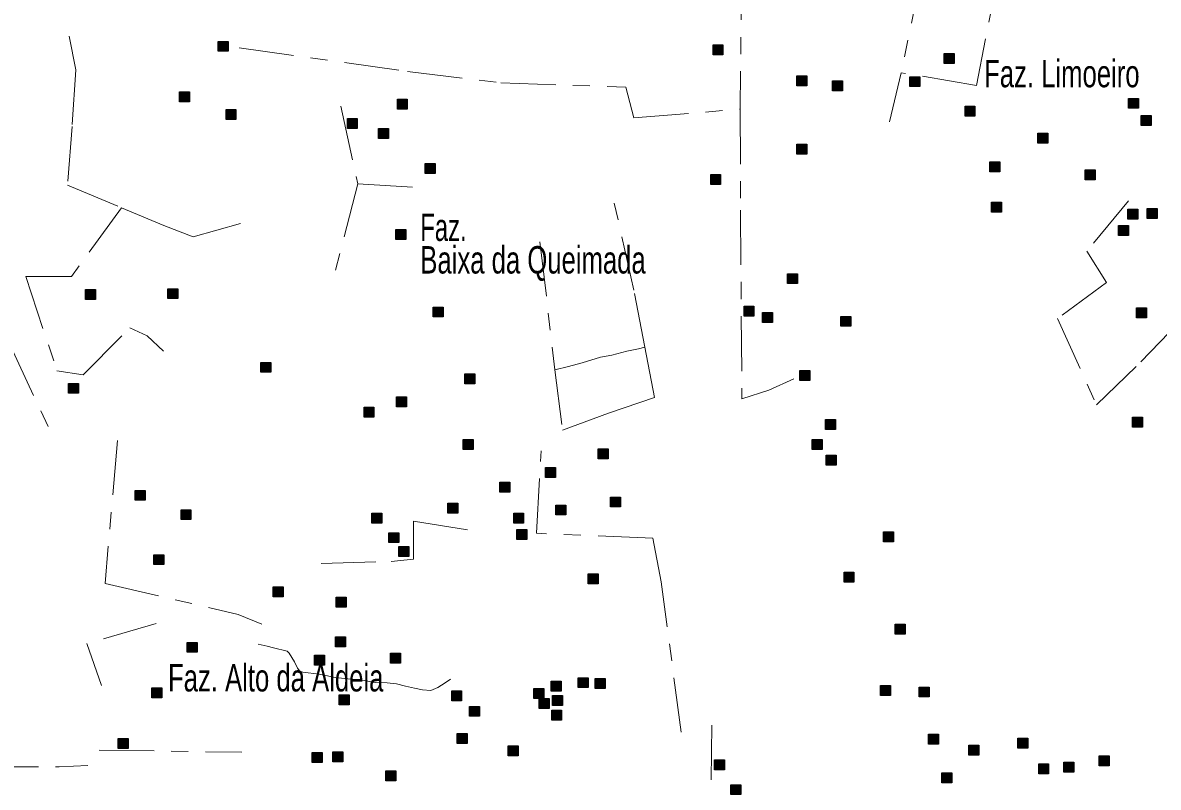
# Model space of a CAD drawing. Extents: x 445.4 to 500, y 8728.7 to 8784.
# Drawn here: x 475.26 to 481.88, y 8770.25 to 8774.71 of the extents above; entities that cross this region are included whole.
import ezdxf

# ---------------------------------------------------------------- set-up
doc = ezdxf.new("R2010")
doc.units = 0
doc.header["$LTSCALE"] = 0.064
doc.linetypes.add('DOT_DASHED', pattern=[7.7, 5, -1.2, 0.3, -1.2])
doc.layers.add('2', color=7, linetype='Continuous', lineweight=25)
doc.layers.add('22', color=7, linetype='DOT_DASHED', lineweight=13)
doc.layers.add('61', color=7, linetype='Continuous')

msp = doc.modelspace()

# ---------------------------------------------------------------- hatches: boundary and pattern name
at = {"layer": '2'}
for points in [[(476.3995, 8774.601), (476.4575, 8774.601), (476.4575, 8774.543), (476.3995, 8774.543)], [(479.2865, 8774.5802), (479.3445, 8774.5802), (479.3445, 8774.5222), (479.2865, 8774.5222)], [(480.635, 8774.5304), (480.693, 8774.5304), (480.693, 8774.4724), (480.635, 8774.4724)], [(479.7752, 8774.3991), (479.8332, 8774.3991), (479.8332, 8774.3411), (479.7752, 8774.3411)], [(479.9838, 8774.3707), (480.0418, 8774.3707), (480.0418, 8774.3127), (479.9838, 8774.3127)], [(480.4359, 8774.3945), (480.4939, 8774.3945), (480.4939, 8774.3365), (480.4359, 8774.3365)], [(476.1733, 8774.3067), (476.2313, 8774.3067), (476.2313, 8774.2487), (476.1733, 8774.2487)], [(477.4448, 8774.2632), (477.5028, 8774.2632), (477.5028, 8774.2052), (477.4448, 8774.2052)], [(481.7119, 8774.2681), (481.7699, 8774.2681), (481.7699, 8774.2101), (481.7119, 8774.2101)], [(476.4448, 8774.2026), (476.5028, 8774.2026), (476.5028, 8774.1446), (476.4448, 8774.1446)], [(480.7571, 8774.2225), (480.8151, 8774.2225), (480.8151, 8774.1645), (480.7571, 8774.1645)], [(477.1529, 8774.1498), (477.2109, 8774.1498), (477.2109, 8774.0918), (477.1529, 8774.0918)], [(481.7843, 8774.1685), (481.8423, 8774.1685), (481.8423, 8774.1105), (481.7843, 8774.1105)], [(477.3353, 8774.0926), (477.3933, 8774.0926), (477.3933, 8774.0346), (477.3353, 8774.0346)], [(481.1825, 8774.0643), (481.2405, 8774.0643), (481.2405, 8774.0063), (481.1825, 8774.0063)], [(479.7752, 8774.0007), (479.8332, 8774.0007), (479.8332, 8773.9427), (479.7752, 8773.9427)], [(477.6077, 8773.8875), (477.6657, 8773.8875), (477.6657, 8773.8295), (477.6077, 8773.8295)], [(480.9019, 8773.8968), (480.9599, 8773.8968), (480.9599, 8773.8388), (480.9019, 8773.8388)], [(481.4585, 8773.8515), (481.5165, 8773.8515), (481.5165, 8773.7935), (481.4585, 8773.7935)], [(479.2729, 8773.8241), (479.3309, 8773.8241), (479.3309, 8773.7661), (479.2729, 8773.7661)], [(480.911, 8773.6614), (480.969, 8773.6614), (480.969, 8773.6034), (480.911, 8773.6034)], [(481.7074, 8773.6206), (481.7654, 8773.6206), (481.7654, 8773.5626), (481.7074, 8773.5626)], [(481.8205, 8773.6252), (481.8785, 8773.6252), (481.8785, 8773.5672), (481.8205, 8773.5672)], [(481.6531, 8773.5256), (481.7111, 8773.5256), (481.7111, 8773.4676), (481.6531, 8773.4676)], [(477.4358, 8773.5026), (477.4938, 8773.5026), (477.4938, 8773.4446), (477.4358, 8773.4446)], [(479.7209, 8773.2446), (479.7789, 8773.2446), (479.7789, 8773.1866), (479.7209, 8773.1866)], [(475.6257, 8773.1523), (475.6837, 8773.1523), (475.6837, 8773.0943), (475.6257, 8773.0943)], [(476.1054, 8773.1568), (476.1634, 8773.1568), (476.1634, 8773.0988), (476.1054, 8773.0988)], [(477.653, 8773.0499), (477.711, 8773.0499), (477.711, 8772.9919), (477.653, 8772.9919)], [(479.4675, 8773.0544), (479.5255, 8773.0544), (479.5255, 8772.9964), (479.4675, 8772.9964)], [(481.7572, 8773.0457), (481.8152, 8773.0457), (481.8152, 8772.9877), (481.7572, 8772.9877)], [(479.5761, 8773.0182), (479.6341, 8773.0182), (479.6341, 8772.9602), (479.5761, 8772.9602)], [(480.0331, 8772.9956), (480.0911, 8772.9956), (480.0911, 8772.9376), (480.0331, 8772.9376)], [(476.6484, 8772.7267), (476.7064, 8772.7267), (476.7064, 8772.6687), (476.6484, 8772.6687)], [(477.8385, 8772.6605), (477.8965, 8772.6605), (477.8965, 8772.6025), (477.8385, 8772.6025)], [(479.7933, 8772.6786), (479.8513, 8772.6786), (479.8513, 8772.6206), (479.7933, 8772.6206)], [(475.5262, 8772.6044), (475.5842, 8772.6044), (475.5842, 8772.5464), (475.5262, 8772.5464)], [(477.4403, 8772.5247), (477.4983, 8772.5247), (477.4983, 8772.4667), (477.4403, 8772.4667)], [(477.2503, 8772.4658), (477.3083, 8772.4658), (477.3083, 8772.4078), (477.2503, 8772.4078)], [(479.9426, 8772.3934), (480.0006, 8772.3934), (480.0006, 8772.3354), (479.9426, 8772.3354)], [(481.7345, 8772.4073), (481.7925, 8772.4073), (481.7925, 8772.3493), (481.7345, 8772.3493)], [(477.8295, 8772.2757), (477.8875, 8772.2757), (477.8875, 8772.2177), (477.8295, 8772.2177)], [(479.8657, 8772.2757), (479.9237, 8772.2757), (479.9237, 8772.2177), (479.8657, 8772.2177)], [(478.6168, 8772.2214), (478.6748, 8772.2214), (478.6748, 8772.1634), (478.6168, 8772.1634)], [(479.9472, 8772.1851), (480.0052, 8772.1851), (480.0052, 8772.1271), (479.9472, 8772.1271)], [(478.3091, 8772.1127), (478.3671, 8772.1127), (478.3671, 8772.0547), (478.3091, 8772.0547)], [(478.0421, 8772.0267), (478.1001, 8772.0267), (478.1001, 8771.9687), (478.0421, 8771.9687)], [(475.9153, 8771.9796), (475.9733, 8771.9796), (475.9733, 8771.9216), (475.9153, 8771.9216)], [(478.6892, 8771.9407), (478.7472, 8771.9407), (478.7472, 8771.8827), (478.6892, 8771.8827)], [(476.1823, 8771.8665), (476.2403, 8771.8665), (476.2403, 8771.8085), (476.1823, 8771.8085)], [(477.739, 8771.9044), (477.797, 8771.9044), (477.797, 8771.8464), (477.739, 8771.8464)], [(478.3692, 8771.8938), (478.4272, 8771.8938), (478.4272, 8771.8358), (478.3692, 8771.8358)], [(477.2955, 8771.8456), (477.3535, 8771.8456), (477.3535, 8771.7876), (477.2955, 8771.7876)], [(478.1236, 8771.8456), (478.1816, 8771.8456), (478.1816, 8771.7876), (478.1236, 8771.7876)], [(477.3951, 8771.7324), (477.4531, 8771.7324), (477.4531, 8771.6744), (477.3951, 8771.6744)], [(478.1417, 8771.7505), (478.1997, 8771.7505), (478.1997, 8771.6925), (478.1417, 8771.6925)], [(480.282, 8771.7369), (480.34, 8771.7369), (480.34, 8771.6789), (480.282, 8771.6789)], [(476.0239, 8771.6039), (476.0819, 8771.6039), (476.0819, 8771.5459), (476.0239, 8771.5459)], [(477.4539, 8771.6509), (477.5119, 8771.6509), (477.5119, 8771.5929), (477.4539, 8771.5929)], [(478.558, 8771.4924), (478.616, 8771.4924), (478.616, 8771.4344), (478.558, 8771.4344)], [(480.0512, 8771.5015), (480.1092, 8771.5015), (480.1092, 8771.4435), (480.0512, 8771.4435)], [(476.7208, 8771.4155), (476.7788, 8771.4155), (476.7788, 8771.3575), (476.7208, 8771.3575)], [(477.0874, 8771.3566), (477.1454, 8771.3566), (477.1454, 8771.2986), (477.0874, 8771.2986)], [(480.3499, 8771.1982), (480.4079, 8771.1982), (480.4079, 8771.1402), (480.3499, 8771.1402)], [(477.0836, 8771.1247), (477.1416, 8771.1247), (477.1416, 8771.0667), (477.0836, 8771.0667)], [(476.2185, 8771.0923), (476.2765, 8771.0923), (476.2765, 8771.0343), (476.2185, 8771.0343)], [(476.9607, 8771.0171), (477.0187, 8771.0171), (477.0187, 8770.9591), (476.9607, 8770.9591)], [(477.4043, 8771.0284), (477.4623, 8771.0284), (477.4623, 8770.9704), (477.4043, 8770.9704)], [(478.3417, 8770.866), (478.3997, 8770.866), (478.3997, 8770.808), (478.3417, 8770.808)], [(478.4992, 8770.8858), (478.5572, 8770.8858), (478.5572, 8770.8278), (478.4992, 8770.8278)], [(478.5987, 8770.8812), (478.6567, 8770.8812), (478.6567, 8770.8232), (478.5987, 8770.8232)], [(476.0123, 8770.8271), (476.0703, 8770.8271), (476.0703, 8770.7691), (476.0123, 8770.7691)], [(477.7616, 8770.8088), (477.8196, 8770.8088), (477.8196, 8770.7508), (477.7616, 8770.7508)], [(478.2412, 8770.8224), (478.2992, 8770.8224), (478.2992, 8770.7644), (478.2412, 8770.7644)], [(480.2639, 8770.8405), (480.3219, 8770.8405), (480.3219, 8770.7825), (480.2639, 8770.7825)], [(480.4902, 8770.8314), (480.5482, 8770.8314), (480.5482, 8770.7734), (480.4902, 8770.7734)], [(477.1055, 8770.7862), (477.1635, 8770.7862), (477.1635, 8770.7282), (477.1055, 8770.7282)], [(478.2729, 8770.7635), (478.3309, 8770.7635), (478.3309, 8770.7055), (478.2729, 8770.7055)], [(478.3498, 8770.7816), (478.4078, 8770.7816), (478.4078, 8770.7236), (478.3498, 8770.7236)], [(477.8657, 8770.7183), (477.9237, 8770.7183), (477.9237, 8770.6603), (477.8657, 8770.6603)], [(478.3453, 8770.6956), (478.4033, 8770.6956), (478.4033, 8770.6376), (478.3453, 8770.6376)], [(475.8158, 8770.5309), (475.8738, 8770.5309), (475.8738, 8770.4729), (475.8158, 8770.4729)], [(477.7933, 8770.5598), (477.8513, 8770.5598), (477.8513, 8770.5018), (477.7933, 8770.5018)], [(480.5445, 8770.5553), (480.6025, 8770.5553), (480.6025, 8770.4973), (480.5445, 8770.4973)], [(481.0648, 8770.5329), (481.1228, 8770.5329), (481.1228, 8770.4749), (481.0648, 8770.4749)], [(478.0919, 8770.4874), (478.1499, 8770.4874), (478.1499, 8770.4294), (478.0919, 8770.4294)], [(480.7798, 8770.4919), (480.8378, 8770.4919), (480.8378, 8770.4339), (480.7798, 8770.4339)], [(476.9483, 8770.449), (477.0063, 8770.449), (477.0063, 8770.391), (476.9483, 8770.391)], [(477.0684, 8770.4521), (477.1264, 8770.4521), (477.1264, 8770.3941), (477.0684, 8770.3941)], [(479.2956, 8770.4059), (479.3536, 8770.4059), (479.3536, 8770.3479), (479.2956, 8770.3479)], [(481.54, 8770.4288), (481.598, 8770.4288), (481.598, 8770.3708), (481.54, 8770.3708)], [(477.377, 8770.3425), (477.435, 8770.3425), (477.435, 8770.2845), (477.377, 8770.2845)], [(480.6227, 8770.3309), (480.6807, 8770.3309), (480.6807, 8770.2729), (480.6227, 8770.2729)], [(481.187, 8770.3835), (481.245, 8770.3835), (481.245, 8770.3255), (481.187, 8770.3255)], [(481.3332, 8770.3919), (481.3912, 8770.3919), (481.3912, 8770.3339), (481.3332, 8770.3339)], [(479.3906, 8770.261), (479.4486, 8770.261), (479.4486, 8770.203), (479.3906, 8770.203)]]:
    msp.add_hatch(color=256, dxfattribs=at).paths.add_polyline_path(points)

# ---------------------------------------------------------------- linework, layer by layer
for points in [[(476.3995, 8774.601), (476.4575, 8774.601), (476.4575, 8774.543), (476.3995, 8774.543)], [(479.2865, 8774.5802), (479.3445, 8774.5802), (479.3445, 8774.5222), (479.2865, 8774.5222)], [(480.635, 8774.5304), (480.693, 8774.5304), (480.693, 8774.4724), (480.635, 8774.4724)], [(479.7752, 8774.3991), (479.8332, 8774.3991), (479.8332, 8774.3411), (479.7752, 8774.3411)], [(479.9838, 8774.3707), (480.0418, 8774.3707), (480.0418, 8774.3127), (479.9838, 8774.3127)], [(480.4359, 8774.3945), (480.4939, 8774.3945), (480.4939, 8774.3365), (480.4359, 8774.3365)], [(476.1733, 8774.3067), (476.2313, 8774.3067), (476.2313, 8774.2487), (476.1733, 8774.2487)], [(477.4448, 8774.2632), (477.5028, 8774.2632), (477.5028, 8774.2052), (477.4448, 8774.2052)], [(481.7119, 8774.2681), (481.7699, 8774.2681), (481.7699, 8774.2101), (481.7119, 8774.2101)], [(476.4448, 8774.2026), (476.5028, 8774.2026), (476.5028, 8774.1446), (476.4448, 8774.1446)], [(480.7571, 8774.2225), (480.8151, 8774.2225), (480.8151, 8774.1645), (480.7571, 8774.1645)], [(477.1529, 8774.1498), (477.2109, 8774.1498), (477.2109, 8774.0918), (477.1529, 8774.0918)], [(481.7843, 8774.1685), (481.8423, 8774.1685), (481.8423, 8774.1105), (481.7843, 8774.1105)], [(477.3353, 8774.0926), (477.3933, 8774.0926), (477.3933, 8774.0346), (477.3353, 8774.0346)], [(481.1825, 8774.0643), (481.2405, 8774.0643), (481.2405, 8774.0063), (481.1825, 8774.0063)], [(479.7752, 8774.0007), (479.8332, 8774.0007), (479.8332, 8773.9427), (479.7752, 8773.9427)], [(477.6077, 8773.8875), (477.6657, 8773.8875), (477.6657, 8773.8295), (477.6077, 8773.8295)], [(480.9019, 8773.8968), (480.9599, 8773.8968), (480.9599, 8773.8388), (480.9019, 8773.8388)], [(481.4585, 8773.8515), (481.5165, 8773.8515), (481.5165, 8773.7935), (481.4585, 8773.7935)], [(479.2729, 8773.8241), (479.3309, 8773.8241), (479.3309, 8773.7661), (479.2729, 8773.7661)], [(480.911, 8773.6614), (480.969, 8773.6614), (480.969, 8773.6034), (480.911, 8773.6034)], [(481.7074, 8773.6206), (481.7654, 8773.6206), (481.7654, 8773.5626), (481.7074, 8773.5626)], [(481.8205, 8773.6252), (481.8785, 8773.6252), (481.8785, 8773.5672), (481.8205, 8773.5672)], [(481.6531, 8773.5256), (481.7111, 8773.5256), (481.7111, 8773.4676), (481.6531, 8773.4676)], [(477.4358, 8773.5026), (477.4938, 8773.5026), (477.4938, 8773.4446), (477.4358, 8773.4446)], [(479.7209, 8773.2446), (479.7789, 8773.2446), (479.7789, 8773.1866), (479.7209, 8773.1866)], [(475.6257, 8773.1523), (475.6837, 8773.1523), (475.6837, 8773.0943), (475.6257, 8773.0943)], [(476.1054, 8773.1568), (476.1634, 8773.1568), (476.1634, 8773.0988), (476.1054, 8773.0988)], [(477.653, 8773.0499), (477.711, 8773.0499), (477.711, 8772.9919), (477.653, 8772.9919)], [(479.4675, 8773.0544), (479.5255, 8773.0544), (479.5255, 8772.9964), (479.4675, 8772.9964)], [(481.7572, 8773.0457), (481.8152, 8773.0457), (481.8152, 8772.9877), (481.7572, 8772.9877)], [(479.5761, 8773.0182), (479.6341, 8773.0182), (479.6341, 8772.9602), (479.5761, 8772.9602)], [(480.0331, 8772.9956), (480.0911, 8772.9956), (480.0911, 8772.9376), (480.0331, 8772.9376)], [(476.6484, 8772.7267), (476.7064, 8772.7267), (476.7064, 8772.6687), (476.6484, 8772.6687)], [(477.8385, 8772.6605), (477.8965, 8772.6605), (477.8965, 8772.6025), (477.8385, 8772.6025)], [(479.7933, 8772.6786), (479.8513, 8772.6786), (479.8513, 8772.6206), (479.7933, 8772.6206)], [(475.5262, 8772.6044), (475.5842, 8772.6044), (475.5842, 8772.5464), (475.5262, 8772.5464)], [(477.4403, 8772.5247), (477.4983, 8772.5247), (477.4983, 8772.4667), (477.4403, 8772.4667)], [(477.2503, 8772.4658), (477.3083, 8772.4658), (477.3083, 8772.4078), (477.2503, 8772.4078)], [(479.9426, 8772.3934), (480.0006, 8772.3934), (480.0006, 8772.3354), (479.9426, 8772.3354)], [(481.7345, 8772.4073), (481.7925, 8772.4073), (481.7925, 8772.3493), (481.7345, 8772.3493)], [(477.8295, 8772.2757), (477.8875, 8772.2757), (477.8875, 8772.2177), (477.8295, 8772.2177)], [(479.8657, 8772.2757), (479.9237, 8772.2757), (479.9237, 8772.2177), (479.8657, 8772.2177)], [(478.6168, 8772.2214), (478.6748, 8772.2214), (478.6748, 8772.1634), (478.6168, 8772.1634)], [(479.9472, 8772.1851), (480.0052, 8772.1851), (480.0052, 8772.1271), (479.9472, 8772.1271)], [(478.3091, 8772.1127), (478.3671, 8772.1127), (478.3671, 8772.0547), (478.3091, 8772.0547)], [(478.0421, 8772.0267), (478.1001, 8772.0267), (478.1001, 8771.9687), (478.0421, 8771.9687)], [(475.9153, 8771.9796), (475.9733, 8771.9796), (475.9733, 8771.9216), (475.9153, 8771.9216)], [(478.6892, 8771.9407), (478.7472, 8771.9407), (478.7472, 8771.8827), (478.6892, 8771.8827)], [(476.1823, 8771.8665), (476.2403, 8771.8665), (476.2403, 8771.8085), (476.1823, 8771.8085)], [(477.739, 8771.9044), (477.797, 8771.9044), (477.797, 8771.8464), (477.739, 8771.8464)], [(478.3692, 8771.8938), (478.4272, 8771.8938), (478.4272, 8771.8358), (478.3692, 8771.8358)], [(477.2955, 8771.8456), (477.3535, 8771.8456), (477.3535, 8771.7876), (477.2955, 8771.7876)], [(478.1236, 8771.8456), (478.1816, 8771.8456), (478.1816, 8771.7876), (478.1236, 8771.7876)], [(477.3951, 8771.7324), (477.4531, 8771.7324), (477.4531, 8771.6744), (477.3951, 8771.6744)], [(478.1417, 8771.7505), (478.1997, 8771.7505), (478.1997, 8771.6925), (478.1417, 8771.6925)], [(480.282, 8771.7369), (480.34, 8771.7369), (480.34, 8771.6789), (480.282, 8771.6789)], [(476.0239, 8771.6039), (476.0819, 8771.6039), (476.0819, 8771.5459), (476.0239, 8771.5459)], [(477.4539, 8771.6509), (477.5119, 8771.6509), (477.5119, 8771.5929), (477.4539, 8771.5929)], [(478.558, 8771.4924), (478.616, 8771.4924), (478.616, 8771.4344), (478.558, 8771.4344)], [(480.0512, 8771.5015), (480.1092, 8771.5015), (480.1092, 8771.4435), (480.0512, 8771.4435)], [(476.7208, 8771.4155), (476.7788, 8771.4155), (476.7788, 8771.3575), (476.7208, 8771.3575)], [(477.0874, 8771.3566), (477.1454, 8771.3566), (477.1454, 8771.2986), (477.0874, 8771.2986)], [(480.3499, 8771.1982), (480.4079, 8771.1982), (480.4079, 8771.1402), (480.3499, 8771.1402)], [(477.0836, 8771.1247), (477.1416, 8771.1247), (477.1416, 8771.0667), (477.0836, 8771.0667)], [(476.2185, 8771.0923), (476.2765, 8771.0923), (476.2765, 8771.0343), (476.2185, 8771.0343)], [(476.9607, 8771.0171), (477.0187, 8771.0171), (477.0187, 8770.9591), (476.9607, 8770.9591)], [(477.4043, 8771.0284), (477.4623, 8771.0284), (477.4623, 8770.9704), (477.4043, 8770.9704)], [(478.3417, 8770.866), (478.3997, 8770.866), (478.3997, 8770.808), (478.3417, 8770.808)], [(478.4992, 8770.8858), (478.5572, 8770.8858), (478.5572, 8770.8278), (478.4992, 8770.8278)], [(478.5987, 8770.8812), (478.6567, 8770.8812), (478.6567, 8770.8232), (478.5987, 8770.8232)], [(476.0123, 8770.8271), (476.0703, 8770.8271), (476.0703, 8770.7691), (476.0123, 8770.7691)], [(477.7616, 8770.8088), (477.8196, 8770.8088), (477.8196, 8770.7508), (477.7616, 8770.7508)], [(478.2412, 8770.8224), (478.2992, 8770.8224), (478.2992, 8770.7644), (478.2412, 8770.7644)], [(480.2639, 8770.8405), (480.3219, 8770.8405), (480.3219, 8770.7825), (480.2639, 8770.7825)], [(480.4902, 8770.8314), (480.5482, 8770.8314), (480.5482, 8770.7734), (480.4902, 8770.7734)], [(477.1055, 8770.7862), (477.1635, 8770.7862), (477.1635, 8770.7282), (477.1055, 8770.7282)], [(478.2729, 8770.7635), (478.3309, 8770.7635), (478.3309, 8770.7055), (478.2729, 8770.7055)], [(478.3498, 8770.7816), (478.4078, 8770.7816), (478.4078, 8770.7236), (478.3498, 8770.7236)], [(477.8657, 8770.7183), (477.9237, 8770.7183), (477.9237, 8770.6603), (477.8657, 8770.6603)], [(478.3453, 8770.6956), (478.4033, 8770.6956), (478.4033, 8770.6376), (478.3453, 8770.6376)], [(475.8158, 8770.5309), (475.8738, 8770.5309), (475.8738, 8770.4729), (475.8158, 8770.4729)], [(477.7933, 8770.5598), (477.8513, 8770.5598), (477.8513, 8770.5018), (477.7933, 8770.5018)], [(480.5445, 8770.5553), (480.6025, 8770.5553), (480.6025, 8770.4973), (480.5445, 8770.4973)], [(481.0648, 8770.5329), (481.1228, 8770.5329), (481.1228, 8770.4749), (481.0648, 8770.4749)], [(478.0919, 8770.4874), (478.1499, 8770.4874), (478.1499, 8770.4294), (478.0919, 8770.4294)], [(480.7798, 8770.4919), (480.8378, 8770.4919), (480.8378, 8770.4339), (480.7798, 8770.4339)], [(476.9483, 8770.449), (477.0063, 8770.449), (477.0063, 8770.391), (476.9483, 8770.391)], [(477.0684, 8770.4521), (477.1264, 8770.4521), (477.1264, 8770.3941), (477.0684, 8770.3941)], [(479.2956, 8770.4059), (479.3536, 8770.4059), (479.3536, 8770.3479), (479.2956, 8770.3479)], [(481.54, 8770.4288), (481.598, 8770.4288), (481.598, 8770.3708), (481.54, 8770.3708)], [(477.377, 8770.3425), (477.435, 8770.3425), (477.435, 8770.2845), (477.377, 8770.2845)], [(480.6227, 8770.3309), (480.6807, 8770.3309), (480.6807, 8770.2729), (480.6227, 8770.2729)], [(481.187, 8770.3835), (481.245, 8770.3835), (481.245, 8770.3255), (481.187, 8770.3255)], [(481.3332, 8770.3919), (481.3912, 8770.3919), (481.3912, 8770.3339), (481.3332, 8770.3339)], [(479.3906, 8770.261), (479.4486, 8770.261), (479.4486, 8770.203), (479.3906, 8770.203)]]:
    msp.add_lwpolyline(points, close=True, dxfattribs=at)
at = {"layer": '22'}
for p, q in [((477.2138, 8773.7693), (477.5962, 8773.746)), ((478.2767, 8773.4309), (478.3644, 8772.6825)), ((479.2801, 8770.6088), (479.2653, 8769.622)), ((475.7049, 8770.4636), (476.5368, 8770.4503))]:
    msp.add_line(p, q, dxfattribs=at)
for points in [[(481.6116, 8776.2868), (481.6575, 8775.9404), (481.2924, 8775.8785), (481.2571, 8775.8483), (481.1663, 8775.2339), (480.9949, 8775.2238), (480.8234, 8774.3426), (480.3847, 8774.4181)], [(480.5658, 8775.3073), (480.5084, 8775.0198), (480.3847, 8774.4181), (480.3157, 8774.1316)], [(479.4489, 8775.0928), (479.453, 8775.0464), (479.4453, 8774.2049)], [(475.53, 8774.6306), (475.5688, 8774.4351), (475.5467, 8774.1042), (475.519, 8773.7622), (475.8353, 8773.629)], [(476.5225, 8774.5637), (477.5046, 8774.4254), (478.0488, 8774.3587), (478.7778, 8774.3331), (478.8241, 8774.1536), (479.4453, 8774.2049)], [(477.115, 8774.2228), (477.2138, 8773.7693), (477.0731, 8773.2274)], [(479.4453, 8774.2049), (479.4472, 8773.6163), (479.455, 8772.5141), (479.6131, 8772.5639), (479.7574, 8772.6313)], [(478.8882, 8772.8148), (478.8246, 8773.1483), (478.7002, 8773.7024)], [(481.7105, 8773.6705), (481.4678, 8773.3765), (481.5817, 8773.1928), (481.297, 8772.9827), (481.5248, 8772.4796), (481.7832, 8772.729), (482.1501, 8773.1117)], [(475.8353, 8773.629), (475.5437, 8773.2289), (475.2767, 8773.2289), (475.4584, 8772.6777), (475.6119, 8772.6537), (475.8835, 8772.9283), (475.9843, 8772.8819), (476.0799, 8772.7928)], [(475.8353, 8773.629), (476.0824, 8773.525), (476.2537, 8773.4588), (476.5284, 8773.5368)], [(474.6312, 8771.8448), (474.2625, 8772.9788), (474.4106, 8773.0211), (474.3824, 8773.1197), (474.9114, 8773.2606), (474.9819, 8773.2747), (475.1865, 8772.8238), (475.4413, 8772.2801)], [(478.3644, 8772.6825), (478.4427, 8772.7034), (478.5224, 8772.7244), (478.6297, 8772.7568), (478.6952, 8772.7696), (478.7842, 8772.7926), (478.8517, 8772.8061), (478.8882, 8772.8148)], [(478.3644, 8772.6825), (478.4085, 8772.3312), (478.6765, 8772.4298), (478.9445, 8772.5214), (478.8882, 8772.8148)], [(475.8124, 8772.2713), (475.7388, 8771.436), (476.5163, 8771.2552), (476.6546, 8771.1975)], [(479.1008, 8770.5681), (478.9839, 8771.4464), (478.9353, 8771.6996), (478.2568, 8771.7288), (478.2843, 8772.2108)], [(476.9996, 8771.553), (477.4081, 8771.5643), (477.5386, 8771.5774), (477.5386, 8771.799), (477.9171, 8771.7403)], [(476.037, 8771.202), (475.6323, 8771.085), (475.7175, 8770.8403)], [(473.7997, 8771.1626), (474.1623, 8771.1407), (474.2963, 8771.0843), (474.7477, 8770.6405), (475.0298, 8770.3658), (475.4711, 8770.3657), (475.6389, 8770.3738)], [(476.6325, 8771.0815), (476.6853, 8771.0692), (476.7228, 8771.0594), (476.8013, 8771.0398), (476.8127, 8771.03), (476.8437, 8770.9793), (476.8617, 8770.9417), (476.8764, 8770.9237), (476.8928, 8770.9172), (476.9891, 8770.9074), (477.0267, 8770.8992), (477.0823, 8770.8878), (477.1754, 8770.878), (477.2391, 8770.8714), (477.3175, 8770.8584), (477.3845, 8770.8567), (477.4401, 8770.8502), (477.4924, 8770.8355), (477.5446, 8770.824), (477.5904, 8770.8142), (477.6394, 8770.811), (477.6802, 8770.8289), (477.7244, 8770.8551), (477.7551, 8770.8768)]]:
    msp.add_lwpolyline(points, dxfattribs=at)

# ---------------------------------------------------------------- texts
at = {"layer": '61'}
for s, width, p in [('Faz. Limoeiro', 0.7, (480.8685, 8774.333)), ('Faz.', 0.65, (477.5785, 8773.4356)), ('Baixa da Queimada', 0.7, (477.5785, 8773.2456)), ('Faz. Alto da Aldeia', 0.7, (476.1063, 8770.8055))]:
    msp.add_text(s, height=0.16, dxfattribs=dict(at, width=width)).set_placement(p)

doc.saveas('drawing.dxf')
